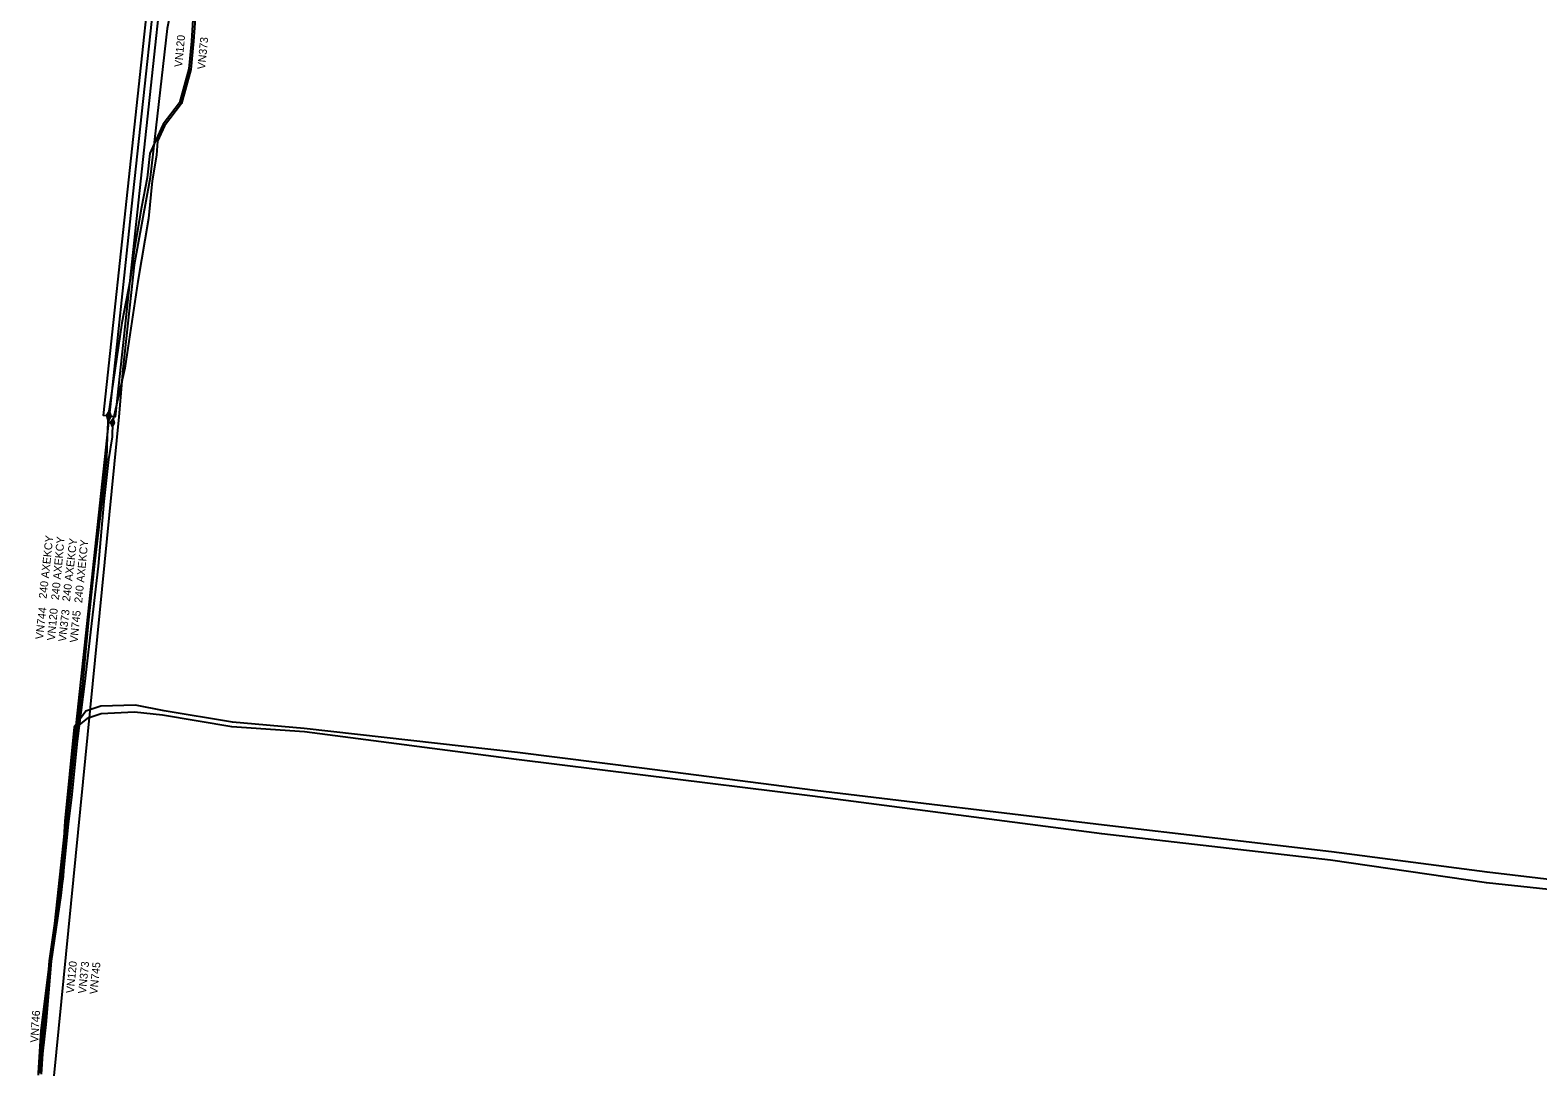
# Model space of a CAD drawing. Extents: x -540879 to -537255, y -1184046 to -1180016.
# Drawn here: x -540110 to -539919.1, y -1184024.6 to -1183892.2 of the extents above; entities that cross this region are included whole.
import ezdxf

# ---------------------------------------------------------------- set-up
doc = ezdxf.new("R2010")
doc.units = 0
for name, color, linetype in [('Vrstva 19', 7, 'Continuous'), ('Vrstva 20', 7, 'Continuous'), ('Vrstva 4', 7, 'Continuous'), ('Vrstva 5', 7, 'Continuous'), ('Vrstva 6', 7, 'Continuous'), ('Vrstva 7', 7, 'Continuous')]:
    doc.layers.add(name, color=color, linetype=linetype)

# ---------------------------------------------------------------- blocks, each defined once
blk = doc.blocks.new('VN870')
at = {"layer": 'Vrstva 4'}
for points in [[(0, -0.25), (0.5, 0), (0, 0.25), (-0.5, 0), (0, -0.25)], [(0.37, 0), (0, 0.19), (-0.36, 0), (0, -0.19), (0.37, 0)], [(0.24, 0), (0, 0.12), (-0.25, 0), (0, -0.12), (0.24, 0)], [(0.12, 0), (0, 0.06), (-0.13, 0), (0, -0.06), (0.12, 0)]]:
    blk.add_lwpolyline(points, dxfattribs=at)

msp = doc.modelspace()

# ---------------------------------------------------------------- linework, layer by layer
at = {"layer": 'Vrstva 20'}
msp.add_lwpolyline([(-540093.72, -1183875.84), (-540092.22, -1183876), (-540099.23, -1183941.17), (-540100.73, -1183941.01)], close=True, dxfattribs=at)
at = {"layer": 'Vrstva 5'}
for points in [[(-540083.24, -1183853.72), (-540083.51, -1183853.39), (-540085.89, -1183855.3), (-540088.39, -1183857.77), (-540090.26, -1183861.36), (-540091.97, -1183870.02), (-540092.97, -1183875.92), (-540097.15, -1183914.52), (-540099.98, -1183941.09), (-540109, -1184024.53)], [(-540084.83, -1183862.39), (-540088.84, -1183864.39), (-540091.38, -1183883.23), (-540091.81, -1183887.85), (-540092.67, -1183892.03), (-540094.81, -1183910.88), (-540096.81, -1183921.97), (-540098.27, -1183935.14), (-540098.77, -1183941.17), (-540106.98, -1184024.6)], [(-540089.31, -1183889.55), (-540089.56, -1183893.63), (-540089.89, -1183897.13), (-540091.07, -1183901.46), (-540093.15, -1183904.15), (-540094.12, -1183906.25), (-540094.83, -1183907.85), (-540095.18, -1183910.93), (-540095.9, -1183914.67), (-540096.78, -1183919.82), (-540097.33, -1183923.85), (-540098.37, -1183929.31), (-540100.1, -1183941.06), (-540100.25, -1183943.62), (-540100.34, -1183946.52), (-540100.93, -1183951.9), (-540101.9, -1183960.12), (-540102.64, -1183967.3), (-540103.35, -1183975), (-540104.29, -1183982.25), (-540104.98, -1183988.92), (-540105.44, -1183992.74), (-540106.2, -1183999.42), (-540106.42, -1184001.79), (-540107.59, -1184010.06), (-540108.21, -1184018.09), (-540108.7, -1184021.85), (-540108.97, -1184024.35)], [(-540089, -1183889.66), (-540089.32, -1183893.65), (-540089.67, -1183897.24), (-540090.85, -1183901.55), (-540092.97, -1183904.36), (-540093.89, -1183906.31), (-540094.01, -1183908.05), (-540094.53, -1183911.31), (-540095.03, -1183916.07), (-540096.36, -1183924.07), (-540098.01, -1183935.04), (-540099.19, -1183940.21), (-540099.56, -1183941.92), (-540099.63, -1183943.7), (-540100.07, -1183946.57), (-540100.66, -1183951.9), (-540101.4, -1183960.11), (-540102.22, -1183967.36), (-540103.11, -1183974.99), (-540104.05, -1183982.24), (-540104.73, -1183989.01), (-540105.2, -1183992.74), (-540105.85, -1183999.47), (-540106.1, -1184001.77), (-540107.35, -1184010.08), (-540108, -1184018.11), (-540108.43, -1184021.83), (-540108.61, -1184024.4)], [(-539910.35, -1184001.07), (-539911.25, -1184000.82), (-539912.68, -1184000.33), (-539925.5, -1183998.8), (-539945.21, -1183996.25), (-539974.01, -1183992.89), (-540010.61, -1183988.47), (-540032.56, -1183985.65), (-540048.3, -1183983.69), (-540075.29, -1183980.65), (-540084.37, -1183979.85), (-540093.04, -1183978.41), (-540096.66, -1183977.69), (-540101.06, -1183977.82), (-540102.93, -1183978.45), (-540104.41, -1183980.48), (-540105.62, -1183992.38), (-540106.03, -1183999.34), (-540107.69, -1184011.08), (-540108.66, -1184018.84), (-540109, -1184024.22)], [(-539905.47, -1184002.3), (-539925.6, -1184000.18), (-539945.37, -1183997.3), (-539974.3, -1183993.95), (-540010.92, -1183989.2), (-540032.75, -1183986.49), (-540048.43, -1183984.55), (-540075.28, -1183981.05), (-540084.47, -1183980.41), (-540093.22, -1183978.93), (-540096.79, -1183978.56), (-540101, -1183978.77), (-540102.76, -1183979.35), (-540104.21, -1183980.5), (-540105.42, -1183992.4), (-540105.83, -1183999.36), (-540107.49, -1184011.1), (-540108.46, -1184018.86), (-540108.8, -1184024.24)]]:
    msp.add_lwpolyline(points, dxfattribs=at)

# ---------------------------------------------------------------- block references
at = {"layer": 'Vrstva 19', "rotation": 83.920286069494}
for p in [(-540100.1, -1183941.06), (-540099.98, -1183941.09), (-540099.56, -1183941.92)]:
    msp.add_blockref('VN870', p, dxfattribs=at)

# ---------------------------------------------------------------- texts
at = {"layer": 'Vrstva 6'}
for rotation, p in [(83.83, (-540107.92, -1183964.24)), (84.732, (-540106.36, -1183964.4)), (83.347, (-540104.96, -1183964.6)), (84.38, (-540103.42, -1183964.78))]:
    msp.add_text('240 AXEKCY', height=1, rotation=rotation, dxfattribs=at).set_placement(p)
at = {"layer": 'Vrstva 7'}
for s, rotation, p in [('VN120', 84.614, (-540090.76, -1183896.97)), ('VN373', 84.432, (-540087.85, -1183897.25)), ('VN744', 83.83, (-540108.36, -1183969.4)), ('VN120', 84.732, (-540106.87, -1183969.54)), ('VN373', 83.547, (-540105.46, -1183969.69)), ('VN745', 84.38, (-540103.99, -1183969.81)), ('VN120', 84.293, (-540104.47, -1184014.19)), ('VN373', 84.202, (-540102.94, -1184014.23)), ('VN745', 84.38, (-540101.49, -1184014.32)), ('VN746', 86.382, (-540109, -1184020.42))]:
    msp.add_text(s, height=1, rotation=rotation, dxfattribs=at).set_placement(p)

doc.saveas('drawing.dxf')
